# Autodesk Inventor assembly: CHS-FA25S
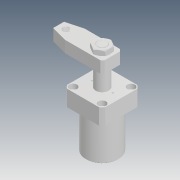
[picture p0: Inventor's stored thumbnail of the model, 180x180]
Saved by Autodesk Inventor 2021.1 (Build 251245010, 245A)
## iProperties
Created: 2019-05
Part Number: CHS-FA25S
Description: STEP AP214
Document SubType Name: Assembly
Designer: user
Title: chs-fa25s_asm.STEP
Revision Number: ÈÎºÎ
Sending System: SolidWorks 2016
Preprocessor: SwSTEP 2.0
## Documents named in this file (5)
- D:\Vault_2016\Projekty\Clamptek\Hydraulic\CHS\CHS-25\Inventor\CHS-FA25S\CHS-FA25S.iam
- D:\Vault_2016\Projekty\Clamptek\Hydraulic\CHS\CHS-25\Inventor\CHS-FA25S\CHS-FA25BT.ipt
- D:\Vault_2016\Projekty\Clamptek\Hydraulic\CHS\CHS-25\Inventor\CHS-FA25S\CHS-25S-02.ipt
- D:\Vault_2016\Projekty\Clamptek\Hydraulic\CHS\CHS-25\Inventor\CHS-FA25S\CHS-25S-01.ipt
- D:\Vault_2016\Projekty\Clamptek\Hydraulic\CHS\CHS-25\Inventor\CHS-FA25S\M14.ipt
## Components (4 placed, 4 different names)
1. CHS-FA25BT_1
2. CHS-25S-02_2
3. CHS-25S-01_3
4. M14_4
